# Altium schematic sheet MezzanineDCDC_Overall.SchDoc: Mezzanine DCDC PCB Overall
size B; Date: 9/7/2021; Engineer: J. Juneau; DocumentNumber: 1006; Revision: 1.2; SheetNumber: 1; SheetTotal: 4
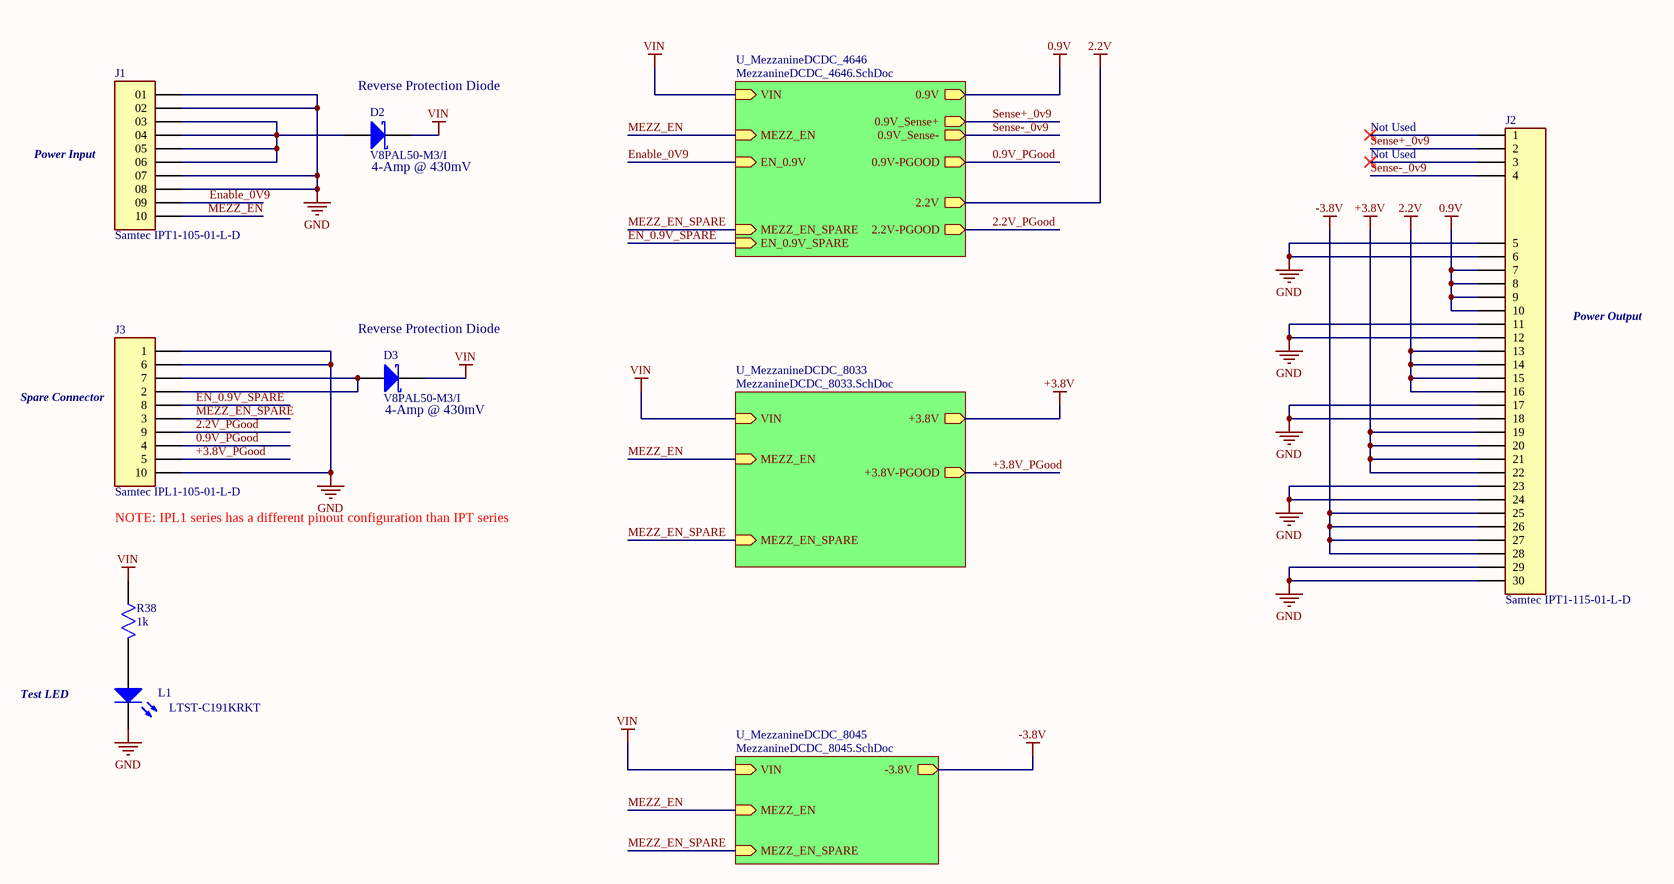
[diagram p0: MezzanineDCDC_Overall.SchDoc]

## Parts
D2  V8PAL50-M3/I  [Schottky Diode V8PAL50-M3/I]
D3  V8PAL50-M3/I  [Schottky Diode V8PAL50-M3/I]
J1  Samtec IPT1-105-01-L-D  [SAMTEC_IPT1-105-01-L-D]
J2  Samtec IPT1-115-01-L-D  [IPT1-115-01-L-D]
J3  Samtec IPL1-105-01-L-D  [IPL1-105-01-L-D]
L1  LTST-C191KRKT  [LED]
R38  value 1k  [Resistor ERJ2G/CRCW 0402]  (hidden comment: ERJ-2GEJ102X)

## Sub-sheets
U_MezzanineDCDC_4646 = MezzanineDCDC_4646.SchDoc: 0.9V (out), VIN (in), 2.2V-PGOOD (out), 2.2V (out), MEZZ_EN (in), EN_0.9V (in), 0.9V_Sense+ (out), 0.9V-PGOOD (out), 0.9V_Sense- (out), MEZZ_EN_SPARE (in), EN_0.9V_SPARE (in)
U_MezzanineDCDC_8033 = MezzanineDCDC_8033.SchDoc: MEZZ_EN (in), VIN (in), +3.8V-PGOOD (out), +3.8V (out), MEZZ_EN_SPARE (in)
U_MezzanineDCDC_8045 = MezzanineDCDC_8045.SchDoc: -3.8V (out), VIN (in), MEZZ_EN (in), MEZZ_EN_SPARE (in)

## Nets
0.9V: J2.7 J2.8 J2.9 J2.10 ; sheet U_MezzanineDCDC_4646/0.9V
2.2V: J2.13 J2.14 J2.15 J2.16 ; sheet U_MezzanineDCDC_4646/2.2V
+3.8V: J2.19 J2.20 J2.21 J2.22 ; sheet U_MezzanineDCDC_8033/+3.8V
-3.8V: J2.25 J2.26 J2.27 J2.28 ; sheet U_MezzanineDCDC_8045/-3.8V
GND: J1.01 J1.02 J1.07 J1.08 J2.5 J2.6 J2.11 J2.12 J2.17 J2.18 J2.23 J2.24 J2.29 J2.30 J3.1 J3.6 J3.10 L1.2(K)
VIN: D2.1(K) D3.1(K) R38.1 ; sheet U_MezzanineDCDC_8033/VIN, sheet U_MezzanineDCDC_8045/VIN, sheet U_MezzanineDCDC_4646/VIN
0.9V_PGood: J3.4 ; sheet U_MezzanineDCDC_4646/0.9V-PGOOD
2.2V_PGood: J3.9 ; sheet U_MezzanineDCDC_4646/2.2V-PGOOD
+3.8V_PGood: J3.5 ; sheet U_MezzanineDCDC_8033/+3.8V-PGOOD
EN_0.9V_SPARE: J3.8 ; sheet U_MezzanineDCDC_4646/EN_0.9V_SPARE
Enable_0V9: J1.09 ; sheet U_MezzanineDCDC_4646/EN_0.9V
MEZZ_EN: J1.10 ; sheet U_MezzanineDCDC_8033/MEZZ_EN, sheet U_MezzanineDCDC_8045/MEZZ_EN, sheet U_MezzanineDCDC_4646/MEZZ_EN
MEZZ_EN_SPARE: J3.3 ; sheet U_MezzanineDCDC_8033/MEZZ_EN_SPARE, sheet U_MezzanineDCDC_8045/MEZZ_EN_SPARE, sheet U_MezzanineDCDC_4646/MEZZ_EN_SPARE
Sense+_0v9: J2.2 ; sheet U_MezzanineDCDC_4646/0.9V_Sense+
Sense-_0v9: J2.4 ; sheet U_MezzanineDCDC_4646/0.9V_Sense-
NetD2_2: D2.2(A) J1.03 J1.04 J1.05 J1.06
NetD3_2: D3.2(A) J3.2 J3.7
NetL1_1: L1.1(A) R38.2

Not connected (* = marked no-connect by the designer): J2 1* 3*

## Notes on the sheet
- (near D2) Reverse Protection Diode
- Power Input
- (near D2) 4-Amp @ 430mV
- Not Used
- Power Output
- (near D3) Reverse Protection Diode
- (near J3) Spare Connector
- (near D3) 4-Amp @ 430mV
- (near J3) NOTE: IPL1 series has a different pinout configuration than IPT series
- Test LED

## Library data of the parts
D2 D3 = Schotkky Diode: Diode Schottky 50V 4A Surface Mount DO-221BC (SMPA)
J1 = Samtec IPT1-105-01-L-D: CONN HEADER VERT 10POS 2.54MM
J2 = Samtec IPT1-115-01-L-D: 15x2 Pin Connector CONN HEADER VERT 30POS 2.54MM
J3 = Samtec IPL1-105-01-L-D: 5x2 Pin connector
L1 = LED: Red 631nm LED Indication - Discrete 2V 0603 (1608 Metric)
R38 = ERJ2G Resistor 0402: RES SMD 1K OHM 5% 1/10W 0402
